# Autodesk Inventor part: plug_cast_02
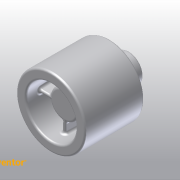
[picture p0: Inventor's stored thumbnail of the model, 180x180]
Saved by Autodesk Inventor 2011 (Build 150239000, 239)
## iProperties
Created: 2002-07
Part Number: plug_cast_02
Document SubType Name: Modeling
Designer: Lieven Grauls
Stock Number: plug_cast_02
Project: Valve Techcamp 2008
Density: 1 g/cm^3
Company: Autodesk
Control State: 0
Master: False
Checked Out: False
Shininess: 64.0
Length Units: 11269
Angle Units: 11279
Time Units: 11290
Mass Units: 11283
Length Display Precision: 3
Angle Display Precision: 2
Density: 0.0
Volumn: 0.0
Area: 0.0
PropertySet Name: Model Information
Author: Lieven Grauls
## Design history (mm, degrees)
sketch "Sketch1"
  geometry: L1 (19, 0)-(26.5, 0); L2 (26.5, 0)-(26.5, 45); L3 (26.5, 45)-(19, 45); L4 (19, 45)-(19, 0); L5 (0, -12)-(0, 72) reference; L6 (0, 60)-(11, 60); L7 (11, 60)-(11, 10); L8 (11, 10)-(0, 10); 1 further point
  constraints: 14 end point, 3 parallel, 3 perpendicular, 2 point on line, 1 horizontal alignment
  dimensions: "d0" = 22 diameter of L6.end L5; "d1" = 38 diameter of L4 L5; "d2" = 53 diameter of L2.end L5; "d3" = 10 distance between parallel lines of L1 L8; "d4" = 45 distance between parallel lines of L3 L1; "d5" = 60 distance between parallel lines of L6 L1
revolve "Revolution1" stored, may be unused: angle "d6" = 90 deg
revolve "Revolution2" stored, may be unused: angle "d7" = 90 deg
fillet "Fillet10" dims "d21" = 2
fillet "Fillet12" dims "d23" = 1
sketch "Sketch2"
  geometry: L1 (-3, 22.607)-(-3, 4.734); L2 (3, 22.607)-(3, 4.734); L3 (0, 37.1)-(0, -37.1) reference; L4 (-3, 22.607)-(3, 22.607); L5 (3, 4.734)-(-3, 4.734)
  constraints: 8 end point, 2 parallel, 1 perpendicular, 1 vertical
  dimensions: "d8" = 6 distance between parallel lines of L2 L1; "d9" = 3 distance between parallel lines of L1 L3 (= 0.5 x d8)
extrude "Extrusion1" join sketch "Sketch2" stored distance "d10" = 10; taper "d11" = -3 deg
fillet "Fillet13" dims "d24" = 2.5
fillet "Fillet8"
fillet "Fillet14" dims "d25" = 2
pattern_circular "Circular Pattern1" dims "d14" = 360 deg
fillet "Fillet1" dims "d15" = 1.5
node "Volumenkörper1"
node "Volumenkörpern"
node "Oberflächenkörpern"
